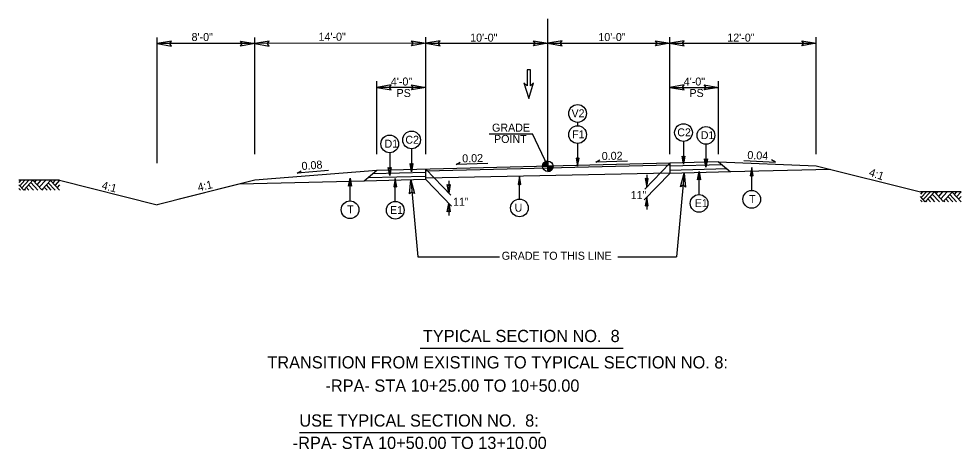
# Model space of a CAD drawing. Extents: x 1901582 to 1902252, y 193723 to 194156.
# Drawn here: x 1902174.6 to 1902251.8, y 193781.9 to 193817.2 of the extents above; entities that cross this region are included whole.
import ezdxf

# ---------------------------------------------------------------- set-up
doc = ezdxf.new("R2010")
doc.units = 0
for name, color, linetype in [('Old_Level_1', 7, 'Continuous'), ('Old_Level_11', 7, 'Continuous'), ('Old_Level_2', 7, 'Continuous'), ('Old_Level_20', 7, 'Continuous'), ('Prop Dimension', 7, 'Continuous'), ('Prop Dimension Text', 7, 'Continuous'), ('Typical Grade Point Symbol CELL', 7, 'Continuous'), ('Typical Pavement Slope Information CELL', 7, 'Continuous'), ('Typical Slope Point Local CELL', 7, 'Continuous'), ('Typical Terminator CELL', 7, 'Continuous'), ('Typical Text General CELL', 7, 'Continuous'), ('Typical Text Grade Point CELL', 7, 'Continuous')]:
    doc.layers.add(name, color=color, linetype=linetype)

# ---------------------------------------------------------------- blocks, each defined once
blk = doc.blocks.new('TERMINATOR')
at = {"layer": 'Typical Terminator CELL'}
blk.add_lwpolyline([(-0.469, 0.081), (0, 0), (-0.471, -0.083), (-0.411, 0)], close=True, dxfattribs=at)

msp = doc.modelspace()

# ---------------------------------------------------------------- linework, layer by layer
at = {"layer": 'Old_Level_1'}
for p, q in [((1902185.898, 193805.348), (1902185.898, 193815.646)), ((1902193.898, 193815.146), (1902185.898, 193815.146)), ((1902227.898, 193805.338), (1902203.897, 193804.738)), ((1902207.898, 193804.712), (1902227.898, 193805.212)), ((1902227.898, 193805.338), (1902225.849, 193803.222)), ((1902231.898, 193805.438), (1902227.898, 193805.338)), ((1902227.898, 193805.338), (1902227.898, 193804.504)), ((1902232.192, 193805.195), (1902227.904, 193805.088)), ((1902231.894, 193805.438), (1902232.887, 193804.629)), ((1902231.898, 193805.438), (1902239.898, 193805.118)), ((1902239.898, 193805.118), (1902248.433, 193802.984)), ((1902203.897, 193804.738), (1902193.898, 193803.938)), ((1902203.897, 193804.738), (1902202.841, 193803.878)), ((1902207.907, 193804.255), (1902203.158, 193804.136)), ((1902207.898, 193804.588), (1902203.58, 193804.48)), ((1902207.898, 193804.014), (1902207.898, 193804.838)), ((1902207.898, 193804.838), (1902209.947, 193802.722)), ((1902227.898, 193804.504), (1902225.792, 193802.328)), ((1902226.007, 193804.384), (1902226.007, 193803.384)), ((1902232.887, 193804.629), (1902227.898, 193804.504)), ((1902232.589, 193804.872), (1902227.912, 193804.755)), ((1902229.089, 193804.534), (1902228.459, 193797.674)), ((1902241.039, 193804.833), (1902232.887, 193804.629)), ((1902177.898, 193803.938), (1902177.898, 193803.938)), ((1902193.898, 193803.938), (1902187.577, 193802.358)), ((1902202.841, 193803.878), (1902192.638, 193803.623)), ((1902207.913, 193804.005), (1902202.841, 193803.878)), ((1902206.667, 193803.974), (1902207.246, 193797.674)), ((1902207.898, 193804.004), (1902210.005, 193801.828)), ((1902209.789, 193803.884), (1902209.789, 193802.884)), ((1902209.789, 193802.051), (1902209.789, 193801.051)), ((1902226.007, 193802.551), (1902226.007, 193801.551)), ((1902207.246, 193797.674), (1902213.933, 193797.674)), ((1902223.64, 193797.674), (1902228.459, 193797.674))]:
    msp.add_line(p, q, dxfattribs=at)
for points in [[(1902207.898, 193804.152), (1902227.89, 193804.552)], [(1902177.898, 193803.938), (1902174.556, 193803.938)], [(1902177.898, 193803.938), (1902185.898, 193801.938)], [(1902193.898, 193803.938), (1902185.898, 193801.938)], [(1902251.775, 193802.984), (1902248.433, 193802.984)]]:
    msp.add_lwpolyline(points, dxfattribs=at)
at = {"layer": 'Old_Level_11'}
for p, q in [((1902217.898, 193805.088), (1902217.898, 193817.16)), ((1902220.342, 193808.686), (1902220.342, 193808.408)), ((1902206.738, 193806.518), (1902206.738, 193804.644)), ((1902220.342, 193806.957), (1902220.342, 193805.083)), ((1902229.022, 193807.124), (1902229.022, 193805.25)), ((1902230.864, 193806.893), (1902230.864, 193805.019)), ((1902204.948, 193806.193), (1902204.948, 193804.319)), ((1902234.609, 193803.106), (1902234.609, 193804.98)), ((1902215.581, 193802.398), (1902215.581, 193804.272)), ((1902230.294, 193802.774), (1902230.294, 193804.648)), ((1902174.726, 193803.938), (1902174.556, 193803.755)), ((1902174.96, 193803.141), (1902174.556, 193803.576)), ((1902175.046, 193803.938), (1902174.632, 193803.494)), ((1902175.379, 193803.938), (1902174.799, 193803.315)), ((1902175.701, 193803.937), (1902174.96, 193803.141)), ((1902175.752, 193803.133), (1902175.352, 193803.562)), ((1902176.122, 193803.133), (1902175.536, 193803.761)), ((1902176.432, 193803.151), (1902175.701, 193803.937)), ((1902175.965, 193803.938), (1902175.832, 193803.795)), ((1902176.367, 193803.938), (1902176.034, 193803.579)), ((1902176.765, 193803.938), (1902176.232, 193803.365)), ((1902177.156, 193803.93), (1902176.432, 193803.151)), ((1902177.215, 193803.133), (1902176.814, 193803.562)), ((1902177.524, 193803.133), (1902176.97, 193803.729)), ((1902177.898, 193803.133), (1902177.156, 193803.93)), ((1902177.523, 193803.938), (1902177.336, 193803.737)), ((1902177.898, 193803.938), (1902177.523, 193803.535)), ((1902177.898, 193803.576), (1902177.692, 193803.354)), ((1902201.695, 193802.251), (1902201.695, 193804.125)), ((1902205.406, 193802.213), (1902205.406, 193804.087)), ((1902174.69, 193803.133), (1902174.556, 193803.276)), ((1902175.091, 193803.133), (1902175.022, 193803.207)), ((1902175.386, 193803.133), (1902175.169, 193803.366)), ((1902176.557, 193803.133), (1902176.486, 193803.209)), ((1902176.868, 193803.133), (1902176.641, 193803.376)), ((1902248.603, 193802.984), (1902248.433, 193802.801)), ((1902248.923, 193802.984), (1902248.509, 193802.54)), ((1902249.256, 193802.984), (1902248.676, 193802.361)), ((1902249.578, 193802.983), (1902248.837, 193802.187)), ((1902249.999, 193802.179), (1902249.413, 193802.807)), ((1902250.309, 193802.197), (1902249.578, 193802.983)), ((1902249.842, 193802.984), (1902249.709, 193802.841)), ((1902250.244, 193802.984), (1902249.911, 193802.625)), ((1902250.642, 193802.984), (1902250.109, 193802.411)), ((1902251.033, 193802.976), (1902250.309, 193802.197)), ((1902251.401, 193802.179), (1902250.847, 193802.775)), ((1902251.775, 193802.179), (1902251.033, 193802.976)), ((1902251.4, 193802.984), (1902251.213, 193802.783)), ((1902251.775, 193802.984), (1902251.4, 193802.581)), ((1902248.837, 193802.187), (1902248.433, 193802.622)), ((1902248.567, 193802.179), (1902248.433, 193802.322)), ((1902248.968, 193802.179), (1902248.899, 193802.253)), ((1902249.263, 193802.179), (1902249.046, 193802.412)), ((1902249.629, 193802.179), (1902249.229, 193802.608)), ((1902250.434, 193802.179), (1902250.363, 193802.255)), ((1902250.745, 193802.179), (1902250.518, 193802.422)), ((1902251.092, 193802.179), (1902250.691, 193802.608)), ((1902251.775, 193802.622), (1902251.569, 193802.4)), ((1902207.456, 193790.196), (1902224.082, 193790.196)), ((1902197.543, 193783.274), (1902217.286, 193783.274))]:
    msp.add_line(p, q, dxfattribs=at)
for points in [[(1902220.226, 193805.755), (1902220.342, 193805.083), (1902220.461, 193805.758), (1902220.342, 193805.672)], [(1902229.137, 193805.921), (1902229.022, 193805.25), (1902228.902, 193805.925), (1902229.022, 193805.839)], [(1902205.064, 193804.99), (1902204.948, 193804.319), (1902204.829, 193804.994), (1902204.948, 193804.908)], [(1902206.854, 193805.316), (1902206.738, 193804.644), (1902206.619, 193805.319), (1902206.738, 193805.234)], [(1902230.98, 193805.69), (1902230.864, 193805.019), (1902230.745, 193805.694), (1902230.864, 193805.608)], [(1902234.725, 193804.309), (1902234.609, 193804.98), (1902234.49, 193804.305), (1902234.609, 193804.391)], [(1902215.697, 193803.601), (1902215.581, 193804.272), (1902215.462, 193803.597), (1902215.581, 193803.683)], [(1902230.178, 193803.976), (1902230.294, 193804.648), (1902230.413, 193803.973), (1902230.294, 193804.058)], [(1902201.579, 193803.454), (1902201.695, 193804.125), (1902201.814, 193803.45), (1902201.695, 193803.536)], [(1902205.521, 193803.416), (1902205.406, 193804.087), (1902205.286, 193803.412), (1902205.406, 193803.498)]]:
    msp.add_lwpolyline(points, close=True, dxfattribs=at)
for centre in [(1902220.342, 193809.411), (1902220.342, 193807.682), (1902229.022, 193807.849), (1902230.864, 193807.618), (1902204.948, 193806.918), (1902206.738, 193807.244), (1902230.294, 193802.048), (1902234.609, 193802.381), (1902201.695, 193801.526), (1902205.405, 193801.488), (1902215.581, 193801.673)]:
    msp.add_circle(centre, 0.725, dxfattribs=at)
at = {"layer": 'Prop Dimension'}
for p, q in [((1902193.898, 193806.072), (1902193.898, 193815.646)), ((1902207.898, 193815.16), (1902193.898, 193815.146)), ((1902207.898, 193806.073), (1902207.898, 193815.66)), ((1902207.898, 193815.16), (1902217.898, 193815.16)), ((1902217.898, 193815.16), (1902227.898, 193815.16)), ((1902227.898, 193806.073), (1902227.898, 193815.66)), ((1902227.898, 193815.16), (1902239.898, 193815.16)), ((1902239.898, 193806.074), (1902239.898, 193815.66)), ((1902203.898, 193806.073), (1902203.898, 193812.047)), ((1902231.898, 193806.073), (1902231.898, 193812.047)), ((1902207.898, 193811.547), (1902203.898, 193811.547)), ((1902227.898, 193811.547), (1902231.898, 193811.547))]:
    msp.add_line(p, q, dxfattribs=at)
msp.add_lwpolyline([(1902216.742, 193811.913), (1902216.471, 193811.663), (1902216.471, 193812.996), (1902216.221, 193812.996), (1902216.221, 193811.663), (1902215.95, 193811.913), (1902216.346, 193810.642)], close=True, dxfattribs=at)
msp.add_lwpolyline([(1902216.742, 193811.913), (1902216.471, 193811.663), (1902216.471, 193812.996), (1902216.221, 193812.996), (1902216.221, 193811.663), (1902215.95, 193811.913), (1902216.346, 193810.642)], close=True, dxfattribs=at)
at = {"layer": 'Typical Grade Point Symbol CELL'}
for p, q in [((1902217.469, 193805.088), (1902217.898, 193805.088)), ((1902217.898, 193805.088), (1902217.898, 193805.518)), ((1902217.899, 193804.658), (1902217.898, 193805.088)), ((1902218.328, 193805.088), (1902217.898, 193805.088)), ((1902217.898, 193805.088), (1902217.899, 193804.658))]:
    msp.add_line(p, q, dxfattribs=at)
for points in [[(1902217.473, 193805.149), (1902217.473, 193805.088)], [(1902217.482, 193805.193), (1902217.482, 193805.088)], [(1902217.491, 193805.222), (1902217.491, 193805.088)], [(1902217.499, 193805.246), (1902217.499, 193805.088)], [(1902217.508, 193805.266), (1902217.508, 193805.088)], [(1902217.516, 193805.285), (1902217.516, 193805.088)], [(1902217.525, 193805.3), (1902217.525, 193805.088)], [(1902217.534, 193805.314), (1902217.534, 193805.088)], [(1902217.542, 193805.328), (1902217.542, 193805.088)], [(1902217.551, 193805.34), (1902217.551, 193805.088)], [(1902217.559, 193805.351), (1902217.559, 193805.088)], [(1902217.568, 193805.362), (1902217.568, 193805.088)], [(1902217.576, 193805.372), (1902217.576, 193805.088)], [(1902217.585, 193805.382), (1902217.585, 193805.088)], [(1902217.594, 193805.391), (1902217.594, 193805.088)], [(1902217.602, 193805.399), (1902217.602, 193805.088)], [(1902217.611, 193805.407), (1902217.611, 193805.088)], [(1902217.619, 193805.414), (1902217.619, 193805.088)], [(1902217.628, 193805.422), (1902217.628, 193805.088)], [(1902217.637, 193805.429), (1902217.637, 193805.088)], [(1902217.645, 193805.434), (1902217.645, 193805.088)], [(1902217.654, 193805.441), (1902217.654, 193805.088)], [(1902217.662, 193805.447), (1902217.662, 193805.088)], [(1902217.671, 193805.453), (1902217.671, 193805.088)], [(1902217.68, 193805.457), (1902217.68, 193805.088)], [(1902217.688, 193805.462), (1902217.688, 193805.088)], [(1902217.697, 193805.467), (1902217.697, 193805.088)], [(1902217.705, 193805.472), (1902217.705, 193805.088)], [(1902217.714, 193805.476), (1902217.714, 193805.088)], [(1902217.723, 193805.479), (1902217.723, 193805.088)], [(1902217.731, 193805.483), (1902217.731, 193805.088)], [(1902217.74, 193805.487), (1902217.74, 193805.088)], [(1902217.748, 193805.491), (1902217.748, 193805.088)], [(1902217.757, 193805.494), (1902217.757, 193805.088)], [(1902217.766, 193805.497), (1902217.766, 193805.088)], [(1902217.774, 193805.499), (1902217.774, 193805.088)], [(1902217.783, 193805.501), (1902217.783, 193805.088)], [(1902217.791, 193805.504), (1902217.791, 193805.088)], [(1902217.8, 193805.506), (1902217.8, 193805.088)], [(1902217.809, 193805.508), (1902217.809, 193805.088)], [(1902217.817, 193805.51), (1902217.817, 193805.088)], [(1902217.826, 193805.512), (1902217.826, 193805.088)], [(1902217.834, 193805.513), (1902217.834, 193805.088)], [(1902217.843, 193805.514), (1902217.843, 193805.088)], [(1902217.852, 193805.515), (1902217.852, 193805.088)], [(1902217.86, 193805.516), (1902217.86, 193805.088)], [(1902217.869, 193805.517), (1902217.869, 193805.088)], [(1902217.877, 193805.517), (1902217.877, 193805.088)], [(1902217.886, 193805.518), (1902217.886, 193805.088)], [(1902217.894, 193805.518), (1902217.894, 193805.518), (1902217.894, 193805.088)], [(1902217.905, 193805.088), (1902217.905, 193804.658), (1902217.905, 193804.658)], [(1902217.914, 193805.088), (1902217.914, 193804.658)], [(1902217.922, 193805.088), (1902217.922, 193804.659)], [(1902217.931, 193805.088), (1902217.931, 193804.659)], [(1902217.939, 193805.088), (1902217.939, 193804.66)], [(1902217.948, 193805.088), (1902217.948, 193804.661)], [(1902217.957, 193805.088), (1902217.957, 193804.662)], [(1902217.965, 193805.088), (1902217.965, 193804.664)], [(1902217.974, 193805.088), (1902217.974, 193804.665)], [(1902217.982, 193805.088), (1902217.982, 193804.667)], [(1902217.991, 193805.088), (1902217.991, 193804.669)], [(1902217.999, 193805.088), (1902217.999, 193804.671)], [(1902218.008, 193805.088), (1902218.008, 193804.673)], [(1902218.017, 193805.088), (1902218.017, 193804.675)], [(1902218.025, 193805.088), (1902218.025, 193804.677)], [(1902218.034, 193805.088), (1902218.034, 193804.68)], [(1902218.042, 193805.088), (1902218.042, 193804.683)], [(1902218.051, 193805.088), (1902218.051, 193804.686)], [(1902218.06, 193805.088), (1902218.06, 193804.69)], [(1902218.068, 193805.088), (1902218.068, 193804.694)], [(1902218.077, 193805.088), (1902218.077, 193804.697)], [(1902218.085, 193805.088), (1902218.085, 193804.701)], [(1902218.094, 193805.088), (1902218.094, 193804.705)], [(1902218.103, 193805.088), (1902218.103, 193804.71)], [(1902218.111, 193805.088), (1902218.111, 193804.715)], [(1902218.12, 193805.088), (1902218.12, 193804.719)], [(1902218.128, 193805.088), (1902218.128, 193804.725)], [(1902218.137, 193805.088), (1902218.137, 193804.731)], [(1902218.146, 193805.088), (1902218.146, 193804.737)], [(1902218.154, 193805.088), (1902218.154, 193804.742)], [(1902218.163, 193805.088), (1902218.163, 193804.749)], [(1902218.171, 193805.088), (1902218.171, 193804.756)], [(1902218.18, 193805.088), (1902218.18, 193804.763)], [(1902218.189, 193805.088), (1902218.189, 193804.771)], [(1902218.197, 193805.088), (1902218.197, 193804.779)], [(1902218.206, 193805.088), (1902218.206, 193804.787)], [(1902218.214, 193805.088), (1902218.214, 193804.797)], [(1902218.223, 193805.088), (1902218.223, 193804.806)], [(1902218.232, 193805.088), (1902218.232, 193804.817)], [(1902218.24, 193805.088), (1902218.24, 193804.827)], [(1902218.249, 193805.088), (1902218.249, 193804.839)], [(1902218.257, 193805.088), (1902218.257, 193804.851)], [(1902218.266, 193805.088), (1902218.266, 193804.864)], [(1902218.274, 193805.088), (1902218.274, 193804.88)], [(1902218.283, 193805.088), (1902218.283, 193804.896)], [(1902218.292, 193805.088), (1902218.292, 193804.914)], [(1902218.3, 193805.088), (1902218.3, 193804.934)], [(1902218.309, 193805.088), (1902218.309, 193804.96)], [(1902218.317, 193805.088), (1902218.317, 193804.99)], [(1902218.326, 193805.088), (1902218.326, 193805.041)]]:
    msp.add_lwpolyline(points, dxfattribs=at)
msp.add_circle((1902217.899, 193805.088), 0.43, dxfattribs=at)
for start, end in [(90.00952, 180.00952), (270.00952, 0.00952)]:
    msp.add_arc((1902217.899, 193805.088), 0.43, start, end, dxfattribs=at)
at = {"layer": 'Typical Pavement Slope Information CELL'}
for p, q in [((1902210.401, 193805.245), (1902210.733, 193805.413)), ((1902212.988, 193805.308), (1902210.401, 193805.245)), ((1902221.836, 193805.434), (1902222.168, 193805.602)), ((1902224.423, 193805.497), (1902221.836, 193805.434)), ((1902233.965, 193805.563), (1902236.55, 193805.434)), ((1902236.55, 193805.434), (1902236.222, 193805.611)), ((1902199.939, 193804.742), (1902197.36, 193804.536)), ((1902197.36, 193804.536), (1902197.682, 193804.723))]:
    msp.add_line(p, q, dxfattribs=at)
at = {"layer": 'Typical Terminator CELL'}
for points in [[(1902187.07, 193815.347), (1902185.898, 193815.146), (1902187.076, 193814.937), (1902186.927, 193815.146)], [(1902192.726, 193815.347), (1902193.898, 193815.146), (1902192.72, 193814.937), (1902192.87, 193815.146)], [(1902195.07, 193815.347), (1902193.898, 193815.146), (1902195.076, 193814.937), (1902194.927, 193815.146)], [(1902206.726, 193815.362), (1902207.898, 193815.16), (1902206.72, 193814.952), (1902206.87, 193815.16)], [(1902209.07, 193815.362), (1902207.898, 193815.16), (1902209.076, 193814.952), (1902208.927, 193815.16)], [(1902216.726, 193815.362), (1902217.898, 193815.16), (1902216.72, 193814.952), (1902216.87, 193815.16)], [(1902219.07, 193815.362), (1902217.898, 193815.16), (1902219.076, 193814.952), (1902218.927, 193815.16)], [(1902226.726, 193815.362), (1902227.898, 193815.16), (1902226.72, 193814.952), (1902226.87, 193815.16)], [(1902229.07, 193815.362), (1902227.898, 193815.16), (1902229.076, 193814.952), (1902228.927, 193815.16)], [(1902238.726, 193815.362), (1902239.898, 193815.16), (1902238.72, 193814.952), (1902238.87, 193815.16)], [(1902205.07, 193811.749), (1902203.898, 193811.547), (1902205.076, 193811.339), (1902204.927, 193811.547)], [(1902206.726, 193811.749), (1902207.898, 193811.547), (1902206.72, 193811.339), (1902206.87, 193811.547)], [(1902229.07, 193811.749), (1902227.898, 193811.547), (1902229.076, 193811.339), (1902228.927, 193811.547)], [(1902230.726, 193811.749), (1902231.898, 193811.547), (1902230.72, 193811.339), (1902230.87, 193811.547)], [(1902228.789, 193803.417), (1902229.089, 193804.534), (1902229.186, 193803.374), (1902228.997, 193803.538)], [(1902206.576, 193802.821), (1902206.667, 193803.974), (1902206.974, 193802.851), (1902206.759, 193802.977)]]:
    msp.add_lwpolyline(points, close=True, dxfattribs=at)
at = {"layer": 'Typical Text Grade Point CELL'}
for p in [(1902213.098, 193807.758), (1902217.898, 193805.088)]:
    msp.add_line(p, (1902216.636, 193807.758), dxfattribs=at)

# ---------------------------------------------------------------- block references
at = {"layer": 'Old_Level_1', "xscale": 1.5}
for p, yscale, rotation in [((1902209.789, 193802.884), 1.5, -90), ((1902226.007, 193803.384), -1.5, -90), ((1902209.789, 193802.051), 1.5, 90), ((1902226.007, 193802.551), -1.5, 90)]:
    msp.add_blockref('TERMINATOR', p, dxfattribs=dict(at, yscale=yscale, rotation=rotation))

# ---------------------------------------------------------------- texts
at = {"layer": 'Old_Level_1'}
for s, p in [('8\'-0"', (1902188.709, 193815.344)), ('4\'-0"', (1902205.043, 193811.7)), ('4\'-0"', (1902229.043, 193811.7))]:
    msp.add_text(s, height=0.656, dxfattribs=at).set_placement(p)
msp.add_text('4:1', height=0.656, rotation=345.24563, dxfattribs=at).set_placement((1902181.298, 193803.242))
at = {"layer": 'Old_Level_11'}
for s, p in [('TYPICAL SECTION NO.  8', (1902207.667, 193790.69)), ('TRANSITION FROM EXISTING TO TYPICAL SECTION NO. 8: ', (1902194.922, 193788.532)), ('-RPA- STA 10+25.00 TO 10+50.00', (1902199.682, 193786.626)), ('USE TYPICAL SECTION NO.  8:', (1902197.543, 193783.768)), ('-RPA- STA 10+50.00 TO 13+10.00', (1902197.003, 193781.937))]:
    msp.add_text(s, height=1, dxfattribs=at).set_placement(p)
at = {"layer": 'Old_Level_2'}
for s, rotation, p in [('0.02', 1.19158, (1902210.894, 193805.406)), ('0.02', 1.19158, (1902222.329, 193805.595)), ('0.04', 357.35093, (1902234.244, 193805.691))]:
    msp.add_text(s, height=0.656, rotation=rotation, dxfattribs=at).set_placement(p)
at = {"layer": 'Old_Level_20'}
for s, height, p in [('V2', 0.6491, (1902219.847, 193809.105)), ('C2', 0.6491, (1902228.516, 193807.543)), ('C2', 0.6491, (1902206.232, 193806.937)), ('F1', 0.6491, (1902219.9, 193807.376)), ('D1', 0.6491, (1902230.441, 193807.312)), ('D1', 0.6491, (1902204.526, 193806.612)), ('11"', 0.6491, (1902224.696, 193802.405)), ('T', 0.649, (1902234.398, 193802.088)), ('T', 0.649, (1902201.467, 193801.233)), ('11"', 0.6491, (1902210.136, 193801.856)), ('U', 0.649, (1902215.186, 193801.369)), ('E1', 0.6491, (1902229.948, 193801.745)), ('E1', 0.6491, (1902204.972, 193801.184))]:
    msp.add_text(s, height=height, dxfattribs=at).set_placement(p)
at = {"layer": 'Prop Dimension Text'}
for s, p in [('14\'-0"', (1902199.114, 193815.371)), ('10\'-0"', (1902211.54, 193815.292)), ('10\'-0"', (1902222.045, 193815.343)), ('12\'-0"', (1902232.611, 193815.295)), ('PS', (1902205.509, 193810.762)), ('PS', (1902229.509, 193810.762))]:
    msp.add_text(s, height=0.656, dxfattribs=at).set_placement(p)
at = {"layer": 'Typical Pavement Slope Information CELL'}
msp.add_text('0.08', height=0.656, rotation=4.80528, dxfattribs=at).set_placement((1902197.753, 193804.771))
at = {"layer": 'Typical Slope Point Local CELL'}
for rotation, p in [(341.09863, (1902244.165, 193804.327)), (13.0197, (1902189.287, 193803.03))]:
    msp.add_text('4:1', height=0.656, rotation=rotation, dxfattribs=at).set_placement(p)
at = {"layer": 'Typical Text General CELL'}
msp.add_text('GRADE TO THIS LINE', height=0.656, dxfattribs=at).set_placement((1902214.123, 193797.432))
at = {"layer": 'Typical Text Grade Point CELL'}
for s, p in [('GRADE', (1902213.33, 193807.923)), ('POINT', (1902213.494, 193806.996))]:
    msp.add_text(s, height=0.656, rotation=360, dxfattribs=at).set_placement(p)

doc.saveas('drawing.dxf')
